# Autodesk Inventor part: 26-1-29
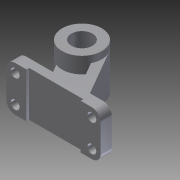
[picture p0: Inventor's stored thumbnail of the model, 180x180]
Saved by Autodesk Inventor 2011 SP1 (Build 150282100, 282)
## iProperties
Created: 2014-01
Part Number: 26-1-29
Document SubType Name: Modeling
Designer: Administrator
Density: 1 g/cm^3
Author: Administrator
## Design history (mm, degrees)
sketch "草图1"
  geometry: C1 r 11.25 at (0, 0); 1 further point
  constraints: 1 centre point, 1 coincident
  dimensions: "d0" = 22.5 diameter of C1
extrude "拉伸1" new body sketch "草图1" stored distance "d1" = 26; taper "d2" = 0 deg
sketch "草图2"
  geometry: C1 r 7 at (0, 0); 1 further point
  constraints: 1 centre point, 1 coincident
  dimensions: "d3" = 14 diameter of C1
extrude "拉伸2" cut sketch "草图2" stored distance "d4" = 17; taper "d5" = 0 deg
hole "Hole1" diameter "d8" = 12; stored, may be unused: countersink angle "d12" = 90 deg, drill point angle "d14" = 118 deg; dims "d6" = 10, "d7" = 10, "d9" = 6, "d10" = 4, "d11" = 2, "d13" = 8
sketch "草图3"
  geometry: L1 (9.743, 5.625)-(26.743, -23.82); L2 (9.743, 5.625)-(43.743, 5.625); L3 (20.969, -23.82)-(10.09, -4.976); L4 (-0.045, 11.25)-(-0.068, 11.289); L5 (26.743, -23.82)-(20.969, -23.82); A1 r 11.25 centre (0, 0) between (9.743, 5.625) and (10.09, -4.976) reference; 1 further point
  constraints: 10 end point, 3 point on circle, 1 equal length, 1 horizontal, 1 parallel, 1 tangent
  dimensions: "d15" = 34 distance of L1.start L1.end; "d16" = 60 deg angle of L1 L2; "d17" = 5 distance between parallel lines of L1 L3
extrude "拉伸3" join sketch "草图3" stored distance "d18" = 18; taper "d19" = 0 deg
sketch "草图4"
  geometry: L1 (-33.726, 3.75)-(19.774, 3.75); L2 (19.774, 3.75)-(19.774, -21.75); L3 (19.774, -21.75)-(-33.726, -21.75); L4 (-33.726, -21.75)-(-33.726, 3.75); 3 further points
  constraints: 8 end point, 2 parallel, 1 horizontal, 1 horizontal alignment, 1 midpoint, 1 perpendicular
  dimensions: "d20" = 25.5 distance of L1.end L2.end; "d21" = 53.5 distance of L1.start L1.end
extrude "拉伸4" join sketch "草图4" distance "d23" = 6.3; taper "d24" = 0 deg
fillet "圆角1" dims "d25" = 5
hole "Hole2" diameter "d28" = 5; stored, may be unused: countersink angle "d32" = 90 deg, drill point angle "d34" = 118 deg; dims "d26" = 10, "d27" = 10, "d29" = 6, "d30" = 4, "d31" = 2, "d33" = 8
mirror "镜像1"
hole "Hole3" diameter "d37" = 5; stored, may be unused: countersink angle "d41" = 90 deg, drill point angle "d43" = 118 deg; dims "d35" = 10, "d36" = 10, "d38" = 6, "d39" = 4, "d40" = 2, "d42" = 8
mirror "镜像2"
sketch "草图5"
  geometry: L1 (-28.726, 3.75)-(14.774, 3.75) reference; L2 (14.774, -21.75)-(-28.726, -21.75) reference; L3 (-22.376, 3.75)-(8.424, 3.75); L4 (8.424, 3.75)-(8.424, -21.75); L5 (8.424, -21.75)-(-22.376, -21.75); L6 (-22.376, -21.75)-(-22.376, 3.75); 2 further points
  constraints: 8 end point, 2 midpoint, 2 parallel, 2 point on line, 1 horizontal, 1 perpendicular
  dimensions: "d44" = 30.8 distance between parallel lines of L4 L6
extrude "拉伸5" cut sketch "草图5" distance "d45" = 1.5; taper "d46" = 0 deg
sketch "草图6"
  geometry: L1 (10.09, -4.976)-(20.969, -23.82) reference; L2 (35.743, -23.82)-(-7.757, -23.82) reference; L3 (-10.257, -23.82)-(-5.257, -23.82) reference; L4 (-12.757, -23.82)-(-7.757, -23.82) reference; L5 (-4.042, -10.499)-(3.649, -23.82); A1 r 11.25 centre (0, 0) between (10.09, -4.976) and (-4.042, -10.499) reference
  constraints: 2 end point, 1 parallel, 1 point on circle, 1 point on line
  dimensions: "d47" = 15 distance between parallel lines of L1 L5
extrude "拉伸6" join sketch "草图6" stored distance "d48" = 7.8; taper "d49" = 0 deg
node "实体1"
